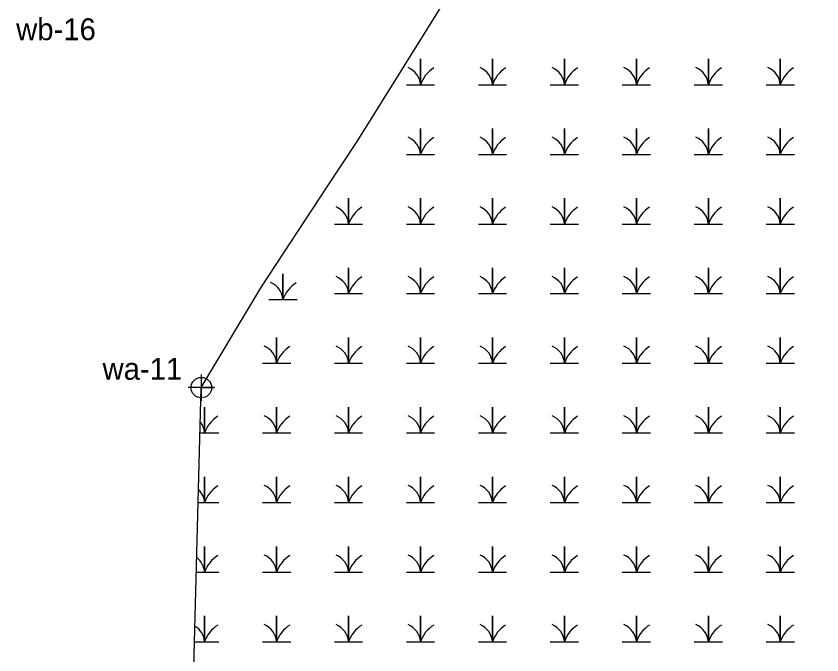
# Model space of a CAD drawing. Extents: x 2379288 to 2381905, y 330670 to 333511.
# Drawn here: x 2379850.3 to 2380034.5, y 331386.1 to 331532.1 of the extents above; entities that cross this region are included whole.
import ezdxf

# ---------------------------------------------------------------- set-up
doc = ezdxf.new("R2010")
doc.units = 0
for name, color, linetype in [('Exist Environmental Wetland Boundary', 7, 'Continuous'), ('Exist Environmental Wetland Boundary Cogo Number', 7, 'Continuous'), ('Exist Environmental Wetland Boundary Cogo Point CELL', 7, 'Continuous'), ('Exist Hydro Swamp or Marsh', 7, 'Continuous')]:
    doc.layers.add(name, color=color, linetype=linetype)

msp = doc.modelspace()

# ---------------------------------------------------------------- linework, layer by layer
at = {"layer": 'Exist Environmental Wetland Boundary'}
msp.add_lwpolyline([(2379969.53, 331242.58), (2379951.18, 331271.07), (2379927.68, 331301.39), (2379890.44, 331365.66), (2379892.64, 331447.19), (2379906.39, 331470.26), (2379921.41, 331493.05), (2379928.27, 331503.45), (2379949.79, 331537.93), (2379979.44, 331586.24), (2380001.81, 331628.04), (2380020.7, 331661.36), (2380049.79, 331711.02), (2380074.34, 331755.11), (2380080.4, 331764.13), (2380105.64, 331802.62), (2380125.36, 331845.41), (2380131.51, 331853.8), (2380135.55, 331859.31), (2380151.44, 331880.98), (2380179.52, 331921.73), (2380190.43, 331937.74), (2380215.91, 331979.8)], dxfattribs=at)
at = {"layer": 'Exist Environmental Wetland Boundary Cogo Point CELL'}
msp.add_lwpolyline([(2379892.64, 331450.19), (2379892.64, 331444.19), (2379892.64, 331447.19), (2379895.64, 331447.19), (2379889.64, 331447.19)], dxfattribs=at)
msp.add_circle((2379892.64, 331447.19), 2.34, dxfattribs=at)
at = {"layer": 'Exist Hydro Swamp or Marsh'}
for points in [[(2379939.52, 331516.42), (2379942.75, 331516.42), (2379942.75, 331522.34), (2379942.75, 331516.42), (2379945.97, 331516.42)], [(2379955.97, 331516.42), (2379959.2, 331516.42), (2379959.2, 331522.34), (2379959.2, 331516.42), (2379962.42, 331516.42)], [(2379972.42, 331516.42), (2379975.65, 331516.42), (2379975.65, 331522.34), (2379975.65, 331516.42), (2379978.87, 331516.42)], [(2379988.87, 331516.42), (2379992.1, 331516.42), (2379992.1, 331522.34), (2379992.1, 331516.42), (2379995.32, 331516.42)], [(2380005.32, 331516.42), (2380008.55, 331516.42), (2380008.55, 331522.34), (2380008.55, 331516.42), (2380011.78, 331516.42)], [(2380021.78, 331516.42), (2380025, 331516.42), (2380025, 331522.34), (2380025, 331516.42), (2380028.23, 331516.42)], [(2379939.52, 331500.5), (2379942.75, 331500.5), (2379942.75, 331506.42), (2379942.75, 331500.5), (2379945.97, 331500.5)], [(2379955.97, 331500.5), (2379959.2, 331500.5), (2379959.2, 331506.42), (2379959.2, 331500.5), (2379962.42, 331500.5)], [(2379972.42, 331500.5), (2379975.65, 331500.5), (2379975.65, 331506.42), (2379975.65, 331500.5), (2379978.87, 331500.5)], [(2379988.87, 331500.5), (2379992.1, 331500.5), (2379992.1, 331506.42), (2379992.1, 331500.5), (2379995.32, 331500.5)], [(2380005.32, 331500.5), (2380008.55, 331500.5), (2380008.55, 331506.42), (2380008.55, 331500.5), (2380011.78, 331500.5)], [(2380021.78, 331500.5), (2380025, 331500.5), (2380025, 331506.42), (2380025, 331500.5), (2380028.23, 331500.5)], [(2379923.07, 331484.58), (2379926.29, 331484.58), (2379926.29, 331490.5), (2379926.29, 331484.58), (2379929.52, 331484.58)], [(2379939.52, 331484.58), (2379942.75, 331484.58), (2379942.75, 331490.5), (2379942.75, 331484.58), (2379945.97, 331484.58)], [(2379955.97, 331484.58), (2379959.2, 331484.58), (2379959.2, 331490.5), (2379959.2, 331484.58), (2379962.42, 331484.58)], [(2379972.42, 331484.58), (2379975.65, 331484.58), (2379975.65, 331490.5), (2379975.65, 331484.58), (2379978.87, 331484.58)], [(2379988.87, 331484.58), (2379992.1, 331484.58), (2379992.1, 331490.5), (2379992.1, 331484.58), (2379995.32, 331484.58)], [(2380005.32, 331484.58), (2380008.55, 331484.58), (2380008.55, 331490.5), (2380008.55, 331484.58), (2380011.78, 331484.58)], [(2380021.78, 331484.58), (2380025, 331484.58), (2380025, 331490.5), (2380025, 331484.58), (2380028.23, 331484.58)], [(2379923.07, 331468.67), (2379926.29, 331468.67), (2379926.29, 331474.58), (2379926.29, 331468.67), (2379929.52, 331468.67)], [(2379939.52, 331468.67), (2379942.75, 331468.67), (2379942.75, 331474.58), (2379942.75, 331468.67), (2379945.97, 331468.67)], [(2379955.97, 331468.67), (2379959.2, 331468.67), (2379959.2, 331474.58), (2379959.2, 331468.67), (2379962.42, 331468.67)], [(2379972.42, 331468.67), (2379975.65, 331468.67), (2379975.65, 331474.58), (2379975.65, 331468.67), (2379978.87, 331468.67)], [(2379988.87, 331468.67), (2379992.1, 331468.67), (2379992.1, 331474.58), (2379992.1, 331468.67), (2379995.32, 331468.67)], [(2380005.32, 331468.67), (2380008.55, 331468.67), (2380008.55, 331474.58), (2380008.55, 331468.67), (2380011.78, 331468.67)], [(2380021.78, 331468.67), (2380025, 331468.67), (2380025, 331474.58), (2380025, 331468.67), (2380028.23, 331468.67)], [(2379908.07, 331467.31), (2379911.29, 331467.31), (2379911.29, 331473.22), (2379911.29, 331467.31), (2379914.52, 331467.31)], [(2379906.62, 331452.75), (2379909.84, 331452.75), (2379909.84, 331458.67), (2379909.84, 331452.75), (2379913.07, 331452.75)], [(2379923.07, 331452.75), (2379926.29, 331452.75), (2379926.29, 331458.67), (2379926.29, 331452.75), (2379929.52, 331452.75)], [(2379939.52, 331452.75), (2379942.75, 331452.75), (2379942.75, 331458.67), (2379942.75, 331452.75), (2379945.97, 331452.75)], [(2379955.97, 331452.75), (2379959.2, 331452.75), (2379959.2, 331458.67), (2379959.2, 331452.75), (2379962.42, 331452.75)], [(2379972.42, 331452.75), (2379975.65, 331452.75), (2379975.65, 331458.67), (2379975.65, 331452.75), (2379978.87, 331452.75)], [(2379988.87, 331452.75), (2379992.1, 331452.75), (2379992.1, 331458.67), (2379992.1, 331452.75), (2379995.32, 331452.75)], [(2380005.32, 331452.75), (2380008.55, 331452.75), (2380008.55, 331458.67), (2380008.55, 331452.75), (2380011.78, 331452.75)], [(2380021.78, 331452.75), (2380025, 331452.75), (2380025, 331458.67), (2380025, 331452.75), (2380028.23, 331452.75)], [(2379892.36, 331436.83), (2379893.39, 331436.83), (2379893.39, 331442.75), (2379893.39, 331436.83), (2379896.62, 331436.83)], [(2379906.62, 331436.83), (2379909.84, 331436.83), (2379909.84, 331442.75), (2379909.84, 331436.83), (2379913.07, 331436.83)], [(2379923.07, 331436.83), (2379926.29, 331436.83), (2379926.29, 331442.75), (2379926.29, 331436.83), (2379929.52, 331436.83)], [(2379939.52, 331436.83), (2379942.75, 331436.83), (2379942.75, 331442.75), (2379942.75, 331436.83), (2379945.97, 331436.83)], [(2379955.97, 331436.83), (2379959.2, 331436.83), (2379959.2, 331442.75), (2379959.2, 331436.83), (2379962.42, 331436.83)], [(2379972.42, 331436.83), (2379975.65, 331436.83), (2379975.65, 331442.75), (2379975.65, 331436.83), (2379978.87, 331436.83)], [(2379988.87, 331436.83), (2379992.1, 331436.83), (2379992.1, 331442.75), (2379992.1, 331436.83), (2379995.32, 331436.83)], [(2380005.32, 331436.83), (2380008.55, 331436.83), (2380008.55, 331442.75), (2380008.55, 331436.83), (2380011.78, 331436.83)], [(2380021.78, 331436.83), (2380025, 331436.83), (2380025, 331442.75), (2380025, 331436.83), (2380028.23, 331436.83)], [(2379891.93, 331420.91), (2379893.39, 331420.91), (2379893.39, 331426.83), (2379893.39, 331420.91), (2379896.62, 331420.91)], [(2379906.62, 331420.91), (2379909.84, 331420.91), (2379909.84, 331426.83), (2379909.84, 331420.91), (2379913.07, 331420.91)], [(2379923.07, 331420.91), (2379926.29, 331420.91), (2379926.29, 331426.83), (2379926.29, 331420.91), (2379929.52, 331420.91)], [(2379939.52, 331420.91), (2379942.75, 331420.91), (2379942.75, 331426.83), (2379942.75, 331420.91), (2379945.97, 331420.91)], [(2379955.97, 331420.91), (2379959.2, 331420.91), (2379959.2, 331426.83), (2379959.2, 331420.91), (2379962.42, 331420.91)], [(2379972.42, 331420.91), (2379975.65, 331420.91), (2379975.65, 331426.83), (2379975.65, 331420.91), (2379978.87, 331420.91)], [(2379988.87, 331420.91), (2379992.1, 331420.91), (2379992.1, 331426.83), (2379992.1, 331420.91), (2379995.32, 331420.91)], [(2380005.32, 331420.91), (2380008.55, 331420.91), (2380008.55, 331426.83), (2380008.55, 331420.91), (2380011.78, 331420.91)], [(2380021.78, 331420.91), (2380025, 331420.91), (2380025, 331426.83), (2380025, 331420.91), (2380028.23, 331420.91)], [(2379891.5, 331405), (2379893.39, 331405), (2379893.39, 331410.91), (2379893.39, 331405), (2379896.62, 331405)], [(2379906.62, 331405), (2379909.84, 331405), (2379909.84, 331410.91), (2379909.84, 331405), (2379913.07, 331405)], [(2379923.07, 331405), (2379926.29, 331405), (2379926.29, 331410.91), (2379926.29, 331405), (2379929.52, 331405)], [(2379939.52, 331405), (2379942.75, 331405), (2379942.75, 331410.91), (2379942.75, 331405), (2379945.97, 331405)], [(2379955.97, 331405), (2379959.2, 331405), (2379959.2, 331410.91), (2379959.2, 331405), (2379962.42, 331405)], [(2379972.42, 331405), (2379975.65, 331405), (2379975.65, 331410.91), (2379975.65, 331405), (2379978.87, 331405)], [(2379988.87, 331405), (2379992.1, 331405), (2379992.1, 331410.91), (2379992.1, 331405), (2379995.32, 331405)], [(2380005.32, 331405), (2380008.55, 331405), (2380008.55, 331410.91), (2380008.55, 331405), (2380011.78, 331405)], [(2380021.78, 331405), (2380025, 331405), (2380025, 331410.91), (2380025, 331405), (2380028.23, 331405)], [(2379891.07, 331389.08), (2379893.39, 331389.08), (2379893.39, 331395), (2379893.39, 331389.08), (2379896.62, 331389.08)], [(2379906.62, 331389.08), (2379909.84, 331389.08), (2379909.84, 331395), (2379909.84, 331389.08), (2379913.07, 331389.08)], [(2379923.07, 331389.08), (2379926.29, 331389.08), (2379926.29, 331395), (2379926.29, 331389.08), (2379929.52, 331389.08)], [(2379939.52, 331389.08), (2379942.75, 331389.08), (2379942.75, 331395), (2379942.75, 331389.08), (2379945.97, 331389.08)], [(2379955.97, 331389.08), (2379959.2, 331389.08), (2379959.2, 331395), (2379959.2, 331389.08), (2379962.42, 331389.08)], [(2379972.42, 331389.08), (2379975.65, 331389.08), (2379975.65, 331395), (2379975.65, 331389.08), (2379978.87, 331389.08)], [(2379988.87, 331389.08), (2379992.1, 331389.08), (2379992.1, 331395), (2379992.1, 331389.08), (2379995.32, 331389.08)], [(2380005.32, 331389.08), (2380008.55, 331389.08), (2380008.55, 331395), (2380008.55, 331389.08), (2380011.78, 331389.08)], [(2380021.78, 331389.08), (2380025, 331389.08), (2380025, 331395), (2380025, 331389.08), (2380028.23, 331389.08)]]:
    msp.add_lwpolyline(points, dxfattribs=at)
for centre, radius, start, end in [((2379938.15, 331516.09), 4.61, 4.1403, 67.535), ((2379954.6, 331516.09), 4.61, 4.1403, 67.535), ((2379971.05, 331516.09), 4.61, 4.1403, 67.535), ((2379987.5, 331516.09), 4.61, 4.1403, 67.535), ((2380003.95, 331516.09), 4.61, 4.1403, 67.535), ((2380020.4, 331516.09), 4.61, 4.1403, 67.535), ((2379949.59, 331514.15), 7.21, 122.1274, 161.6222), ((2379966.04, 331514.15), 7.21, 122.1274, 161.6222), ((2379982.49, 331514.15), 7.21, 122.1274, 161.6222), ((2379998.94, 331514.15), 7.21, 122.1274, 161.6222), ((2380015.39, 331514.15), 7.21, 122.1274, 161.6222), ((2380031.84, 331514.15), 7.21, 122.1274, 161.6222), ((2379938.15, 331500.17), 4.61, 4.1403, 67.535), ((2379949.59, 331498.23), 7.21, 122.1274, 161.6222), ((2379954.6, 331500.17), 4.61, 4.1403, 67.535), ((2379966.04, 331498.23), 7.21, 122.1274, 161.6222), ((2379971.05, 331500.17), 4.61, 4.1403, 67.535), ((2379982.49, 331498.23), 7.21, 122.1274, 161.6222), ((2379987.5, 331500.17), 4.61, 4.1403, 67.535), ((2379998.94, 331498.23), 7.21, 122.1274, 161.6222), ((2380003.95, 331500.17), 4.61, 4.1403, 67.535), ((2380015.39, 331498.23), 7.21, 122.1274, 161.6222), ((2380020.4, 331500.17), 4.61, 4.1403, 67.535), ((2380031.84, 331498.23), 7.21, 122.1274, 161.6222), ((2379921.69, 331484.25), 4.61, 4.1403, 67.535), ((2379933.14, 331482.31), 7.21, 122.1274, 161.6222), ((2379938.15, 331484.25), 4.61, 4.1403, 67.535), ((2379949.59, 331482.31), 7.21, 122.1274, 161.6222), ((2379954.6, 331484.25), 4.61, 4.1403, 67.535), ((2379966.04, 331482.31), 7.21, 122.1274, 161.6222), ((2379971.05, 331484.25), 4.61, 4.1403, 67.535), ((2379982.49, 331482.31), 7.21, 122.1274, 161.6222), ((2379987.5, 331484.25), 4.61, 4.1403, 67.535), ((2379998.94, 331482.31), 7.21, 122.1274, 161.6222), ((2380003.95, 331484.25), 4.61, 4.1403, 67.535), ((2380015.39, 331482.31), 7.21, 122.1274, 161.6222), ((2380020.4, 331484.25), 4.61, 4.1403, 67.535), ((2380031.84, 331482.31), 7.21, 122.1274, 161.6222), ((2379921.69, 331468.33), 4.61, 4.1403, 67.535), ((2379933.14, 331466.39), 7.21, 122.1274, 161.6222), ((2379938.15, 331468.33), 4.61, 4.1403, 67.535), ((2379949.59, 331466.39), 7.21, 122.1274, 161.6222), ((2379954.6, 331468.33), 4.61, 4.1403, 67.535), ((2379966.04, 331466.39), 7.21, 122.1274, 161.6222), ((2379971.05, 331468.33), 4.61, 4.1403, 67.535), ((2379982.49, 331466.39), 7.21, 122.1274, 161.6222), ((2379987.5, 331468.33), 4.61, 4.1403, 67.535), ((2379998.94, 331466.39), 7.21, 122.1274, 161.6222), ((2380003.95, 331468.33), 4.61, 4.1403, 67.535), ((2380015.39, 331466.39), 7.21, 122.1274, 161.6222), ((2380020.4, 331468.33), 4.61, 4.1403, 67.535), ((2380031.84, 331466.39), 7.21, 122.1274, 161.6222), ((2379906.69, 331466.97), 4.61, 4.1403, 67.535), ((2379918.14, 331465.03), 7.21, 122.1274, 161.6222), ((2379905.24, 331452.42), 4.61, 4.1403, 67.535), ((2379916.68, 331450.48), 7.21, 122.1274, 161.6222), ((2379921.69, 331452.42), 4.61, 4.1403, 67.535), ((2379933.14, 331450.48), 7.21, 122.1274, 161.6222), ((2379938.15, 331452.42), 4.61, 4.1403, 67.535), ((2379949.59, 331450.48), 7.21, 122.1274, 161.6222), ((2379954.6, 331452.42), 4.61, 4.1403, 67.535), ((2379966.04, 331450.48), 7.21, 122.1274, 161.6222), ((2379971.05, 331452.42), 4.61, 4.1403, 67.535), ((2379982.49, 331450.48), 7.21, 122.1274, 161.6222), ((2379987.5, 331452.42), 4.61, 4.1403, 67.535), ((2379998.94, 331450.48), 7.21, 122.1274, 161.6222), ((2380003.95, 331452.42), 4.61, 4.1403, 67.535), ((2380015.39, 331450.48), 7.21, 122.1274, 161.6222), ((2380020.4, 331452.42), 4.61, 4.1403, 67.535), ((2380031.84, 331450.48), 7.21, 122.1274, 161.6222), ((2379888.79, 331436.5), 4.61, 4.1403, 37.8884), ((2379900.23, 331434.56), 7.21, 122.1274, 161.6222), ((2379905.24, 331436.5), 4.61, 4.1403, 67.535), ((2379916.68, 331434.56), 7.21, 122.1274, 161.6222), ((2379921.69, 331436.5), 4.61, 4.1403, 67.535), ((2379933.14, 331434.56), 7.21, 122.1274, 161.6222), ((2379938.15, 331436.5), 4.61, 4.1403, 67.535), ((2379949.59, 331434.56), 7.21, 122.1274, 161.6222), ((2379954.6, 331436.5), 4.61, 4.1403, 67.535), ((2379966.04, 331434.56), 7.21, 122.1274, 161.6222), ((2379971.05, 331436.5), 4.61, 4.1403, 67.535), ((2379982.49, 331434.56), 7.21, 122.1274, 161.6222), ((2379987.5, 331436.5), 4.61, 4.1403, 67.535), ((2379998.94, 331434.56), 7.21, 122.1274, 161.6222), ((2380003.95, 331436.5), 4.61, 4.1403, 67.535), ((2380015.39, 331434.56), 7.21, 122.1274, 161.6222), ((2380020.4, 331436.5), 4.61, 4.1403, 67.535), ((2380031.84, 331434.56), 7.21, 122.1274, 161.6222), ((2379900.23, 331418.64), 7.21, 122.1274, 161.6222), ((2379905.24, 331420.58), 4.61, 4.1403, 67.535), ((2379916.68, 331418.64), 7.21, 122.1274, 161.6222), ((2379921.69, 331420.58), 4.61, 4.1403, 67.535), ((2379933.14, 331418.64), 7.21, 122.1274, 161.6222), ((2379938.15, 331420.58), 4.61, 4.1403, 67.535), ((2379949.59, 331418.64), 7.21, 122.1274, 161.6222), ((2379954.6, 331420.58), 4.61, 4.1403, 67.535), ((2379966.04, 331418.64), 7.21, 122.1274, 161.6222), ((2379971.05, 331420.58), 4.61, 4.1403, 67.535), ((2379982.49, 331418.64), 7.21, 122.1274, 161.6222), ((2379987.5, 331420.58), 4.61, 4.1403, 67.535), ((2379998.94, 331418.64), 7.21, 122.1274, 161.6222), ((2380003.95, 331420.58), 4.61, 4.1403, 67.535), ((2380015.39, 331418.64), 7.21, 122.1274, 161.6222), ((2380020.4, 331420.58), 4.61, 4.1403, 67.535), ((2380031.84, 331418.64), 7.21, 122.1274, 161.6222), ((2379888.79, 331420.58), 4.61, 4.1403, 45.6987), ((2379888.79, 331404.66), 4.61, 4.1403, 52.6239), ((2379900.23, 331402.72), 7.21, 122.1274, 161.6222), ((2379905.24, 331404.66), 4.61, 4.1403, 67.535), ((2379916.68, 331402.72), 7.21, 122.1274, 161.6222), ((2379921.69, 331404.66), 4.61, 4.1403, 67.535), ((2379933.14, 331402.72), 7.21, 122.1274, 161.6222), ((2379938.15, 331404.66), 4.61, 4.1403, 67.535), ((2379949.59, 331402.72), 7.21, 122.1274, 161.6222), ((2379954.6, 331404.66), 4.61, 4.1403, 67.535), ((2379966.04, 331402.72), 7.21, 122.1274, 161.6222), ((2379971.05, 331404.66), 4.61, 4.1403, 67.535), ((2379982.49, 331402.72), 7.21, 122.1274, 161.6222), ((2379987.5, 331404.66), 4.61, 4.1403, 67.535), ((2379998.94, 331402.72), 7.21, 122.1274, 161.6222), ((2380003.95, 331404.66), 4.61, 4.1403, 67.535), ((2380015.39, 331402.72), 7.21, 122.1274, 161.6222), ((2380020.4, 331404.66), 4.61, 4.1403, 67.535), ((2380031.84, 331402.72), 7.21, 122.1274, 161.6222), ((2379888.79, 331388.75), 4.61, 4.1403, 58.9888), ((2379900.23, 331386.81), 7.21, 122.1274, 161.6222), ((2379905.24, 331388.75), 4.61, 4.1403, 67.535), ((2379916.68, 331386.81), 7.21, 122.1274, 161.6222), ((2379921.69, 331388.75), 4.61, 4.1403, 67.535), ((2379933.14, 331386.81), 7.21, 122.1274, 161.6222), ((2379938.15, 331388.75), 4.61, 4.1403, 67.535), ((2379949.59, 331386.81), 7.21, 122.1274, 161.6222), ((2379954.6, 331388.75), 4.61, 4.1403, 67.535), ((2379966.04, 331386.81), 7.21, 122.1274, 161.6222), ((2379971.05, 331388.75), 4.61, 4.1403, 67.535), ((2379982.49, 331386.81), 7.21, 122.1274, 161.6222), ((2379987.5, 331388.75), 4.61, 4.1403, 67.535), ((2379998.94, 331386.81), 7.21, 122.1274, 161.6222), ((2380003.95, 331388.75), 4.61, 4.1403, 67.535), ((2380015.39, 331386.81), 7.21, 122.1274, 161.6222), ((2380020.4, 331388.75), 4.61, 4.1403, 67.535), ((2380031.84, 331386.81), 7.21, 122.1274, 161.6222)]:
    msp.add_arc(centre, radius, start, end, dxfattribs=at)

# ---------------------------------------------------------------- texts
at = {"layer": 'Exist Environmental Wetland Boundary Cogo Number'}
for s, p in [('wb-16', (2379850.31, 331526.6)), ('wa-11', (2379870.06, 331448.99))]:
    msp.add_text(s, height=5, dxfattribs=at).set_placement(p)

doc.saveas('drawing.dxf')
